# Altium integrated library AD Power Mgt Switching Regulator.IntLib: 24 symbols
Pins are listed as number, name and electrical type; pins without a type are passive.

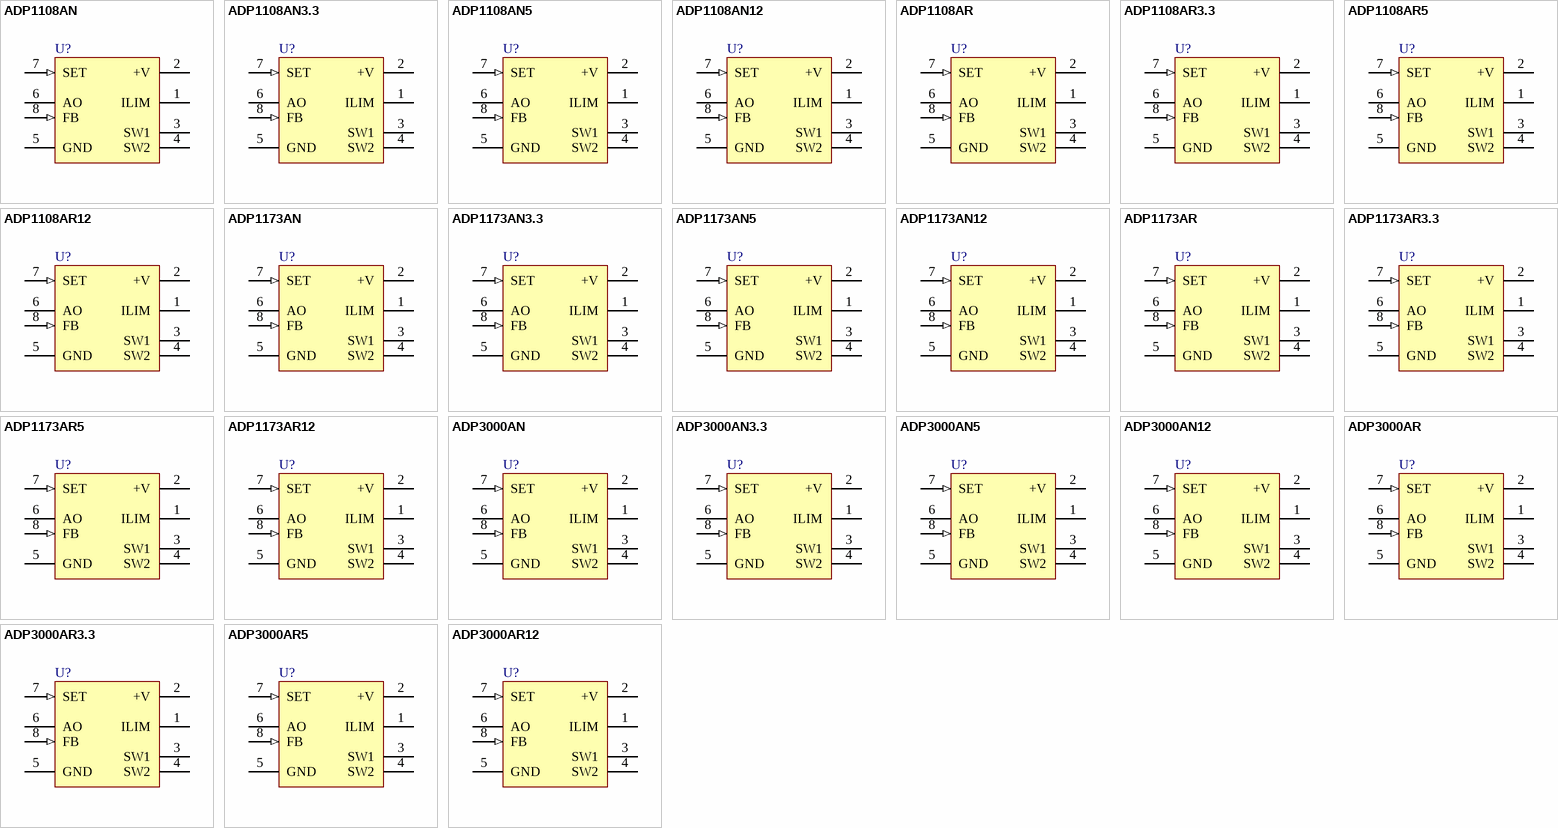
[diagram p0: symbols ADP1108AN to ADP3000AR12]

## ADP1108AN
designator U?
Micropower DC-DC Converter Adjustable and Fixed 3.3V, 5V, 12V
footprint N-8_A (DIP, 8-Leads, Row Spacing 7.62mm, Pitch 2.54mm, Body 9.88x6.61mm)
3D model N-8A (DIP, 8-Pin, Row Spacing 7.62 mm, Pitch 2.54 mm)
pins: 1 ILIM, 2 +V (power), 3 SW1, 4 SW2, 5 GND (power), 6 AO (oc), 7 SET (in), 8 FB (in)

## ADP1108AN3.3
designator U?
Micropower DC-DC Converter Adjustable and Fixed 3.3V, 5V, 12V
footprint N-8_A (DIP, 8-Leads, Row Spacing 7.62mm, Pitch 2.54mm, Body 9.88x6.61mm)
3D model N-8A (DIP, 8-Pin, Row Spacing 7.62 mm, Pitch 2.54 mm)
pins: 1 ILIM, 2 +V (power), 3 SW1, 4 SW2, 5 GND (power), 6 AO (oc), 7 SET (in), 8 FB (in)

## ADP1108AN5
designator U?
Micropower DC-DC Converter Adjustable and Fixed 3.3V, 5V, 12V
footprint N-8_A (DIP, 8-Leads, Row Spacing 7.62mm, Pitch 2.54mm, Body 9.88x6.61mm)
3D model N-8A (DIP, 8-Pin, Row Spacing 7.62 mm, Pitch 2.54 mm)
pins: 1 ILIM, 2 +V (power), 3 SW1, 4 SW2, 5 GND (power), 6 AO (oc), 7 SET (in), 8 FB (in)

## ADP1108AN12
designator U?
Micropower DC-DC Converter Adjustable and Fixed 3.3V, 5V, 12V
footprint N-8_A (DIP, 8-Leads, Row Spacing 7.62mm, Pitch 2.54mm, Body 9.88x6.61mm)
3D model N-8A (DIP, 8-Pin, Row Spacing 7.62 mm, Pitch 2.54 mm)
pins: 1 ILIM, 2 +V (power), 3 SW1, 4 SW2, 5 GND (power), 6 AO (oc), 7 SET (in), 8 FB (in)

## ADP1108AR
designator U?
Micropower DC-DC Converter Adjustable and Fixed 3.3V, 5V, 12V
footprint SO-8_N (SOIC, 8-Leads, Body 4.9x3.9mm, Pitch 1.27mm, IPC Medium Density)
footprint SO-8_L (SOIC, 8-Leads, Body 4.9x3.9mm, Pitch 1.27mm, IPC High Density)
footprint SO-8_M (SOIC, 8-Leads, Body 4.9x3.9mm, Pitch 1.27mm, IPC Low Density)
3D model SO-8 (8-Pin Small Outline Integrated Circuit 1.27 mm Pitch)
pins: 1 ILIM, 2 +V (power), 3 SW1, 4 SW2, 5 GND (power), 6 AO (oc), 7 SET (in), 8 FB (in)

## ADP1108AR3.3
designator U?
Micropower DC-DC Converter Adjustable and Fixed 3.3V, 5V, 12V
footprint SO-8_N (SOIC, 8-Leads, Body 4.9x3.9mm, Pitch 1.27mm, IPC Medium Density)
footprint SO-8_L (SOIC, 8-Leads, Body 4.9x3.9mm, Pitch 1.27mm, IPC High Density)
footprint SO-8_M (SOIC, 8-Leads, Body 4.9x3.9mm, Pitch 1.27mm, IPC Low Density)
3D model SO-8 (8-Pin Small Outline Integrated Circuit 1.27 mm Pitch)
pins: 1 ILIM, 2 +V (power), 3 SW1, 4 SW2, 5 GND (power), 6 AO (oc), 7 SET (in), 8 FB (in)

## ADP1108AR5
designator U?
Micropower DC-DC Converter Adjustable and Fixed 3.3V, 5V, 12V
footprint SO-8_N (SOIC, 8-Leads, Body 4.9x3.9mm, Pitch 1.27mm, IPC Medium Density)
footprint SO-8_L (SOIC, 8-Leads, Body 4.9x3.9mm, Pitch 1.27mm, IPC High Density)
footprint SO-8_M (SOIC, 8-Leads, Body 4.9x3.9mm, Pitch 1.27mm, IPC Low Density)
3D model SO-8 (8-Pin Small Outline Integrated Circuit 1.27 mm Pitch)
pins: 1 ILIM, 2 +V (power), 3 SW1, 4 SW2, 5 GND (power), 6 AO (oc), 7 SET (in), 8 FB (in)

## ADP1108AR12
designator U?
Micropower DC-DC Converter Adjustable and Fixed 3.3V, 5V, 12V
footprint SO-8_N (SOIC, 8-Leads, Body 4.9x3.9mm, Pitch 1.27mm, IPC Medium Density)
footprint SO-8_L (SOIC, 8-Leads, Body 4.9x3.9mm, Pitch 1.27mm, IPC High Density)
footprint SO-8_M (SOIC, 8-Leads, Body 4.9x3.9mm, Pitch 1.27mm, IPC Low Density)
3D model SO-8 (8-Pin Small Outline Integrated Circuit 1.27 mm Pitch)
pins: 1 ILIM, 2 +V (power), 3 SW1, 4 SW2, 5 GND (power), 6 AO (oc), 7 SET (in), 8 FB (in)

## ADP1173AN
designator U?
Micropower DC-DC Converter
footprint N-8_A (DIP, 8-Leads, Row Spacing 7.62mm, Pitch 2.54mm, Body 9.88x6.61mm)
3D model N-8A (DIP, 8-Pin, Row Spacing 7.62 mm, Pitch 2.54 mm)
pins: 1 ILIM, 2 +V (power), 3 SW1, 4 SW2, 5 GND (power), 6 AO (oc), 7 SET (in), 8 FB (in)

## ADP1173AN3.3
designator U?
Micropower DC-DC Converter
footprint N-8_A (DIP, 8-Leads, Row Spacing 7.62mm, Pitch 2.54mm, Body 9.88x6.61mm)
3D model N-8A (DIP, 8-Pin, Row Spacing 7.62 mm, Pitch 2.54 mm)
pins: 1 ILIM, 2 +V (power), 3 SW1, 4 SW2, 5 GND (power), 6 AO (oc), 7 SET (in), 8 FB (in)

## ADP1173AN5
designator U?
Micropower DC-DC Converter
footprint N-8_A (DIP, 8-Leads, Row Spacing 7.62mm, Pitch 2.54mm, Body 9.88x6.61mm)
3D model N-8A (DIP, 8-Pin, Row Spacing 7.62 mm, Pitch 2.54 mm)
pins: 1 ILIM, 2 +V (power), 3 SW1, 4 SW2, 5 GND (power), 6 AO (oc), 7 SET (in), 8 FB (in)

## ADP1173AN12
designator U?
Micropower DC-DC Converter
footprint N-8_A (DIP, 8-Leads, Row Spacing 7.62mm, Pitch 2.54mm, Body 9.88x6.61mm)
3D model N-8A (DIP, 8-Pin, Row Spacing 7.62 mm, Pitch 2.54 mm)
pins: 1 ILIM, 2 +V (power), 3 SW1, 4 SW2, 5 GND (power), 6 AO (oc), 7 SET (in), 8 FB (in)

## ADP1173AR
designator U?
Micropower DC-DC Converter
footprint SO-8_N (SOIC, 8-Leads, Body 4.9x3.9mm, Pitch 1.27mm, IPC Medium Density)
footprint SO-8_L (SOIC, 8-Leads, Body 4.9x3.9mm, Pitch 1.27mm, IPC High Density)
footprint SO-8_M (SOIC, 8-Leads, Body 4.9x3.9mm, Pitch 1.27mm, IPC Low Density)
3D model SO-8 (8-Pin Small Outline Integrated Circuit 1.27 mm Pitch)
pins: 1 ILIM, 2 +V (power), 3 SW1, 4 SW2, 5 GND (power), 6 AO (oc), 7 SET (in), 8 FB (in)

## ADP1173AR3.3
designator U?
Micropower DC-DC Converter
footprint SO-8_N (SOIC, 8-Leads, Body 4.9x3.9mm, Pitch 1.27mm, IPC Medium Density)
footprint SO-8_L (SOIC, 8-Leads, Body 4.9x3.9mm, Pitch 1.27mm, IPC High Density)
footprint SO-8_M (SOIC, 8-Leads, Body 4.9x3.9mm, Pitch 1.27mm, IPC Low Density)
3D model SO-8 (8-Pin Small Outline Integrated Circuit 1.27 mm Pitch)
pins: 1 ILIM, 2 +V (power), 3 SW1, 4 SW2, 5 GND (power), 6 AO (oc), 7 SET (in), 8 FB (in)

## ADP1173AR5
designator U?
Micropower DC-DC Converter
footprint SO-8_N (SOIC, 8-Leads, Body 4.9x3.9mm, Pitch 1.27mm, IPC Medium Density)
footprint SO-8_L (SOIC, 8-Leads, Body 4.9x3.9mm, Pitch 1.27mm, IPC High Density)
footprint SO-8_M (SOIC, 8-Leads, Body 4.9x3.9mm, Pitch 1.27mm, IPC Low Density)
3D model SO-8 (8-Pin Small Outline Integrated Circuit 1.27 mm Pitch)
pins: 1 ILIM, 2 +V (power), 3 SW1, 4 SW2, 5 GND (power), 6 AO (oc), 7 SET (in), 8 FB (in)

## ADP1173AR12
designator U?
Micropower DC-DC Converter
footprint SO-8_N (SOIC, 8-Leads, Body 4.9x3.9mm, Pitch 1.27mm, IPC Medium Density)
footprint SO-8_L (SOIC, 8-Leads, Body 4.9x3.9mm, Pitch 1.27mm, IPC High Density)
footprint SO-8_M (SOIC, 8-Leads, Body 4.9x3.9mm, Pitch 1.27mm, IPC Low Density)
3D model SO-8 (8-Pin Small Outline Integrated Circuit 1.27 mm Pitch)
pins: 1 ILIM, 2 +V (power), 3 SW1, 4 SW2, 5 GND (power), 6 AO (oc), 7 SET (in), 8 FB (in)

## ADP3000AN
designator U?
Micropower Step-Up/Step-Down Fixed 3.3V, 5V, 12V & Adjustable High-Frequency Switching Regulator
footprint N-8_A (DIP, 8-Leads, Row Spacing 7.62mm, Pitch 2.54mm, Body 9.88x6.61mm)
3D model N-8A (DIP, 8-Pin, Row Spacing 7.62 mm, Pitch 2.54 mm)
pins: 1 ILIM, 2 +V (power), 3 SW1, 4 SW2, 5 GND (power), 6 AO (oc), 7 SET (in), 8 FB (in)

## ADP3000AN3.3
designator U?
Micropower Step-Up/Step-Down Fixed 3.3V, 5V, 12V & Adjustable High-Frequency Switching Regulator
footprint N-8_A (DIP, 8-Leads, Row Spacing 7.62mm, Pitch 2.54mm, Body 9.88x6.61mm)
3D model N-8A (DIP, 8-Pin, Row Spacing 7.62 mm, Pitch 2.54 mm)
pins: 1 ILIM, 2 +V (power), 3 SW1, 4 SW2, 5 GND (power), 6 AO (oc), 7 SET (in), 8 FB (in)

## ADP3000AN5
designator U?
Micropower Step-Up/Step-Down Fixed 3.3V, 5V, 12V & Adjustable High-Frequency Switching Regulator
footprint N-8_A (DIP, 8-Leads, Row Spacing 7.62mm, Pitch 2.54mm, Body 9.88x6.61mm)
3D model N-8A (DIP, 8-Pin, Row Spacing 7.62 mm, Pitch 2.54 mm)
pins: 1 ILIM, 2 +V (power), 3 SW1, 4 SW2, 5 GND (power), 6 AO (oc), 7 SET (in), 8 FB (in)

## ADP3000AN12
designator U?
Micropower Step-Up/Step-Down Fixed 3.3V, 5V, 12V & Adjustable High-Frequency Switching Regulator
footprint N-8_A (DIP, 8-Leads, Row Spacing 7.62mm, Pitch 2.54mm, Body 9.88x6.61mm)
3D model N-8A (DIP, 8-Pin, Row Spacing 7.62 mm, Pitch 2.54 mm)
pins: 1 ILIM, 2 +V (power), 3 SW1, 4 SW2, 5 GND (power), 6 AO (oc), 7 SET (in), 8 FB (in)

## ADP3000AR
designator U?
Micropower Step-Up/Step-Down Fixed 3.3V, 5V, 12V & Adjustable High-Frequency Switching Regulator
footprint SO-8_N (SOIC, 8-Leads, Body 4.9x3.9mm, Pitch 1.27mm, IPC Medium Density)
footprint SO-8_L (SOIC, 8-Leads, Body 4.9x3.9mm, Pitch 1.27mm, IPC High Density)
footprint SO-8_M (SOIC, 8-Leads, Body 4.9x3.9mm, Pitch 1.27mm, IPC Low Density)
3D model SO-8 (8-Pin Small Outline Integrated Circuit 1.27 mm Pitch)
pins: 1 ILIM, 2 +V (power), 3 SW1, 4 SW2, 5 GND (power), 6 AO (oc), 7 SET (in), 8 FB (in)

## ADP3000AR3.3
designator U?
Micropower Step-Up/Step-Down Fixed 3.3V, 5V, 12V & Adjustable High-Frequency Switching Regulator
footprint SO-8_N (SOIC, 8-Leads, Body 4.9x3.9mm, Pitch 1.27mm, IPC Medium Density)
footprint SO-8_L (SOIC, 8-Leads, Body 4.9x3.9mm, Pitch 1.27mm, IPC High Density)
footprint SO-8_M (SOIC, 8-Leads, Body 4.9x3.9mm, Pitch 1.27mm, IPC Low Density)
3D model SO-8 (8-Pin Small Outline Integrated Circuit 1.27 mm Pitch)
pins: 1 ILIM, 2 +V (power), 3 SW1, 4 SW2, 5 GND (power), 6 AO (oc), 7 SET (in), 8 FB (in)

## ADP3000AR5
designator U?
Micropower Step-Up/Step-Down Fixed 3.3V, 5V, 12V & Adjustable High-Frequency Switching Regulator
footprint SO-8_N (SOIC, 8-Leads, Body 4.9x3.9mm, Pitch 1.27mm, IPC Medium Density)
footprint SO-8_L (SOIC, 8-Leads, Body 4.9x3.9mm, Pitch 1.27mm, IPC High Density)
footprint SO-8_M (SOIC, 8-Leads, Body 4.9x3.9mm, Pitch 1.27mm, IPC Low Density)
3D model SO-8 (8-Pin Small Outline Integrated Circuit 1.27 mm Pitch)
pins: 1 ILIM, 2 +V (power), 3 SW1, 4 SW2, 5 GND (power), 6 AO (oc), 7 SET (in), 8 FB (in)

## ADP3000AR12
designator U?
Micropower Step-Up/Step-Down Fixed 3.3V, 5V, 12V & Adjustable High-Frequency Switching Regulator
footprint SO-8_N (SOIC, 8-Leads, Body 4.9x3.9mm, Pitch 1.27mm, IPC Medium Density)
footprint SO-8_L (SOIC, 8-Leads, Body 4.9x3.9mm, Pitch 1.27mm, IPC High Density)
footprint SO-8_M (SOIC, 8-Leads, Body 4.9x3.9mm, Pitch 1.27mm, IPC Low Density)
3D model SO-8 (8-Pin Small Outline Integrated Circuit 1.27 mm Pitch)
pins: 1 ILIM, 2 +V (power), 3 SW1, 4 SW2, 5 GND (power), 6 AO (oc), 7 SET (in), 8 FB (in)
